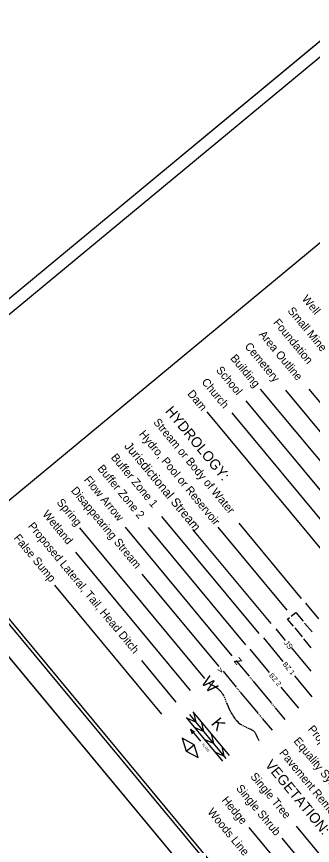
# Model space of a CAD drawing. Extents: x 2054826 to 2060231, y 685508 to 690809.
# Drawn here: x 2056065 to 2056542, y 687304 to 688643 of the extents above; entities that cross this region are included whole.
import ezdxf

# ---------------------------------------------------------------- set-up
doc = ezdxf.new("R2010")
doc.units = 0
for name, color, linetype in [('Sheet Cutting Line CELL', 7, 'Continuous'), ('Sheet Plot Border Inside CELL', 7, 'Continuous'), ('Sheet Plot Border Outside CELL', 7, 'Continuous'), ('Sheet Symbology CELL', 7, 'Continuous')]:
    doc.layers.add(name, color=color, linetype=linetype)

msp = doc.modelspace()

# ---------------------------------------------------------------- linework, layer by layer
at = {"layer": 'Sheet Cutting Line CELL'}
for p, q in [((2057038.3, 689004.2), (2055768.2, 687951)), ((2055768.2, 687951), (2057380.6, 686006.5))]:
    msp.add_line(p, q, dxfattribs=at)
at = {"layer": 'Sheet Plot Border Inside CELL'}
msp.add_lwpolyline([(2055806.5, 687957.4), (2057402.2, 686033.2), (2058620.5, 687043.5), (2057024.8, 688967.7)], close=True, dxfattribs=at)
at = {"layer": 'Sheet Plot Border Outside CELL'}
msp.add_lwpolyline([(2055768.2, 687951), (2057380.6, 686006.5), (2058650.7, 687059.8), (2057038.3, 689004.2)], close=True, dxfattribs=at)
at = {"layer": 'Sheet Symbology CELL'}
for p, q in [((2056657.4, 687801.5), (2056458.5, 688041.3)), ((2056680.5, 687820.7), (2056499.1, 688039.4)), ((2056703.6, 687839.8), (2056536.6, 688041.3)), ((2056634.3, 687782.4), (2056435.4, 688022.2)), ((2056588.1, 687744.1), (2056372.3, 688004.4)), ((2056611.2, 687763.2), (2056412.4, 688003)), ((2056456.2, 687646.6), (2056299.4, 687835.7)), ((2056524.5, 687703.3), (2056424, 687824.5)), ((2056368.6, 687573.9), (2056167, 687817)), ((2056412.6, 687610.4), (2056240.4, 687818.1)), ((2056434.4, 687628.5), (2056277.6, 687817.6)), ((2056475.4, 687662.5), (2056349.3, 687814.4)), ((2056501.4, 687684.1), (2056390, 687818.5)), ((2056345.5, 687554.8), (2056160.5, 687777.9)), ((2056391.7, 687593.1), (2056267.7, 687742.6)), ((2056299.3, 687516.5), (2056126.7, 687724.7)), ((2056530.8, 687695.8), (2056551.9, 687670.3)), ((2056507.9, 687674.7), (2056515.1, 687680.7)), ((2056515.1, 687680.7), (2056527.1, 687666.3)), ((2056529.5, 687663.4), (2056541.5, 687649)), ((2056526, 687641), (2056514, 687655.5)), ((2056462.9, 687639.5), (2056494.3, 687601.6)), ((2056540.3, 687623.7), (2056528.4, 687638.2)), ((2056441, 687621.3), (2056472.4, 687583.4)), ((2056322.4, 687535.6), (2056266.7, 687602.8)), ((2056418.8, 687602.9), (2056439.9, 687577.5)), ((2056397.9, 687585.6), (2056419, 687560.1)), ((2056440.9, 687576.3), (2056441.8, 687575.2)), ((2056442.8, 687574), (2056443.7, 687572.9)), ((2056444.7, 687571.7), (2056445.7, 687570.6)), ((2056446.6, 687569.4), (2056475.3, 687534.8)), ((2056541.9, 687544.2), (2056513.8, 687578.1)), ((2056420, 687559), (2056420.9, 687557.8)), ((2056421.9, 687556.7), (2056422.8, 687555.5)), ((2056423.8, 687554.4), (2056424.7, 687553.2)), ((2056520, 687526), (2056491.9, 687559.9)), ((2056425.7, 687552.1), (2056454.4, 687517.4)), ((2056402, 687538.3), (2056402.5, 687536.9)), ((2056476.3, 687533.6), (2056477.3, 687532.5)), ((2056478.2, 687531.3), (2056479.2, 687530.2)), ((2056480.1, 687529), (2056481.1, 687527.8)), ((2056482, 687526.7), (2056497.8, 687507.7)), ((2056343.6, 687515.8), (2056402.3, 687445)), ((2056349.4, 687520.1), (2056407.8, 687449.6)), ((2056350.3, 687519), (2056354.1, 687503.2)), ((2056455.4, 687516.3), (2056456.3, 687515.1)), ((2056457.3, 687514), (2056458.3, 687512.8)), ((2056338.5, 687511), (2056396.9, 687440.6)), ((2056354.1, 687503.2), (2056339.6, 687509.7)), ((2056362.5, 687504.4), (2056366.3, 687488.5)), ((2056459.2, 687511.7), (2056460.2, 687510.5)), ((2056461.1, 687509.3), (2056476.9, 687490.3)), ((2056345.5, 687492), (2056361.5, 687472.8)), ((2056345.5, 687492), (2056351.7, 687487.8)), ((2056345.5, 687492), (2056347.9, 687484.6)), ((2056366.3, 687488.5), (2056351.8, 687495)), ((2056429.4, 687498.3), (2056430.7, 687497.6)), ((2056432.1, 687496.8), (2056433.4, 687496.2)), ((2056351.3, 687467), (2056332.2, 687477.6)), ((2056332.2, 687477.6), (2056338.5, 687456.4)), ((2056382.5, 687468.9), (2056368.1, 687475.3)), ((2056378.7, 687484.8), (2056382.5, 687468.9)), ((2056338.5, 687456.4), (2056351.3, 687467)), ((2056357.7, 687446.3), (2056351.3, 687467)), ((2056395.7, 687464.3), (2056399.3, 687448.6)), ((2056338.5, 687456.4), (2056357.7, 687446.3)), ((2056399.3, 687448.6), (2056385, 687455)), ((2056643.6, 687087.9), (2056440, 687333.5)), ((2056689.8, 687126.2), (2056516.4, 687335.3)), ((2056666.7, 687107.1), (2056493.3, 687316.2))]:
    msp.add_line(p, q, dxfattribs=at)
msp.add_lwpolyline([(2058605.6, 687055.5), (2057169.3, 688787.4), (2055958.1, 687783), (2057394.3, 686051.1)], close=True, dxfattribs=at)
for points in [[(2056511.6, 687658.4), (2056502.1, 687669.9), (2056505, 687672.3)], [(2056482.8, 687653.9), (2056498.2, 687635.5)], [(2056507.8, 687623.9), (2056521.2, 687607.7)], [(2056521.2, 687607.7), (2056539.4, 687585.7)], [(2056374.8, 687566.4), (2056378.9, 687564.3), (2056383, 687562.1), (2056384, 687561.6), (2056385.7, 687560.5), (2056387, 687559.7), (2056388.8, 687558.3), (2056390.5, 687556.8), (2056391.8, 687555.6), (2056393, 687554.4), (2056393.9, 687553.3), (2056394.8, 687552.3), (2056396.1, 687550.5), (2056397, 687549.1), (2056397.7, 687548), (2056398.6, 687546.4), (2056399.2, 687545.2)], [(2056399.8, 687543.8), (2056400.1, 687543.2), (2056400.4, 687542.5)], [(2056400.9, 687541.1), (2056401.1, 687540.5), (2056401.4, 687539.7)], [(2056403, 687535.4), (2056403.5, 687534.3), (2056404.3, 687532.3), (2056406.1, 687528.5), (2056407.4, 687525.7), (2056409.5, 687521.5), (2056411.7, 687517.4), (2056413, 687515.1), (2056414.2, 687513.2), (2056415.3, 687511.5), (2056416.3, 687510.1), (2056417.2, 687508.8), (2056418, 687507.8), (2056419.5, 687506), (2056420.7, 687504.7), (2056421.7, 687503.8), (2056423.1, 687502.5), (2056424.7, 687501.3), (2056425.9, 687500.4), (2056427, 687499.7), (2056428.1, 687499)], [(2056434.7, 687495.5), (2056435, 687495.3), (2056436.1, 687494.8)], [(2056437.4, 687494.2), (2056438.2, 687493.9), (2056441.2, 687492.6), (2056442.8, 687491.9), (2056444.2, 687491.1), (2056445.3, 687490.4), (2056446.2, 687489.8), (2056446.9, 687489.2), (2056447.5, 687488.7), (2056448.5, 687487.6), (2056449.2, 687486.7), (2056449.7, 687486.1), (2056450.3, 687485.1), (2056450.9, 687484), (2056453.2, 687479), (2056455.4, 687473.9)]]:
    msp.add_lwpolyline(points, dxfattribs=at)

# ---------------------------------------------------------------- texts
for s, height, rotation, p in [('Well', 13.13, 309.6672, (2056524.3, 688186.4)), ('Small Mine', 13.13, 309.6672, (2056501.2, 688167.2)), ('Foundation', 13.13, 309.6672, (2056478.1, 688148.1)), ('Area Outline', 13.125, 309.6672, (2056455, 688128.9)), ('Cemetery', 13.13, 309.6672, (2056431.9, 688109.8)), ('Building', 13.13, 309.6672, (2056408.9, 688090.6)), ('School', 13.13, 309.6672, (2056385.8, 688071.5)), ('Church', 13.13, 309.6672, (2056362.5, 688052.2)), ('Dam', 13.13, 309.6672, (2056339.6, 688033.2)), ('HYDROLOGY:', 16.5, 309.6672, (2056303.6, 688005)), ('Stream or Body of Water', 13.125, 309.6672, (2056284.7, 687987.2)), ('Hydro, Pool or Reservoir', 13.125, 309.6672, (2056261.6, 687968)), ('Jurisdictional Stream', 14.469, 309.6672, (2056237.6, 687948.7)), ('Buffer Zone 1', 13.125, 309.6672, (2056216.3, 687930.5)), ('Buffer Zone 2', 13.125, 309.6672, (2056194.6, 687912.4)), ('Flow Arrow', 13.13, 309.6672, (2056172.8, 687894.3)), ('Disappearing Stream', 13.125, 309.6672, (2056151.9, 687877)), ('Spring', 13.13, 309.6672, (2056128.8, 687857.8)), ('Wetland', 13.13, 309.6672, (2056105.7, 687838.7)), ('Proposed Lateral, Tail, Head Ditch', 13.125, 309.6672, (2056082.6, 687819.5)), ('False Sump', 13.13, 309.6672, (2056059.5, 687800.4)), ('JS', 8.86, 309.6672, (2056495.4, 687631)), ('z', 15, 129.6672, (2056429.4, 687601.9)), ('BZ 1', 7.97, 309.6672, (2056493.5, 687596.7)), ('v', 9.9, 39.4264, (2056393.6, 687582)), ('BZ 2', 7.97, 309.6672, (2056471.6, 687578.6)), ('W', 19.1, 309.6672, (2056361.4, 687567.7)), ('K', 19.1, 309.6672, (2056377.8, 687500.9)), ('Proposed Cable Guiderail', 13.125, 309.6672, (2056534, 687491.7)), ('Equality Symbol', 13.125, 309.6672, (2056510.9, 687472.5)), ('FLOW', 3.89, 309.6672, (2056363.7, 687466.9)), ('Pavement Removal', 13.125, 309.6672, (2056487.8, 687453.4)), ('VEGETATION:', 16.5, 309.6672, (2056464.6, 687434.2)), ('Single Tree', 13.125, 309.6672, (2056441.2, 687415.3)), ('Single Shrub', 13.125, 309.6672, (2056418.1, 687396.2)), ('Hedge', 13.13, 309.6672, (2056395.1, 687377)), ('Woods Line', 13.13, 309.6672, (2056372, 687357.9))]:
    msp.add_text(s, height=height, rotation=rotation, dxfattribs=at).set_placement(p)

doc.saveas('drawing.dxf')
